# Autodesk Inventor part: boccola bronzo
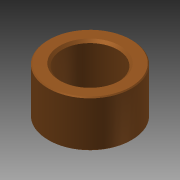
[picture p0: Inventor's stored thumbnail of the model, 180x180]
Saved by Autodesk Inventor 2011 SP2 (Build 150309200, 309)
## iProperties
Created: 2018-03
Part Number: boccola bronzo
Document SubType Name: Modeling
Designer: 18619647
Density: 1 g/cm^3
Author: 18619647
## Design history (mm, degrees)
sketch "Schizzo1"
  geometry: C1 r 6 at (0, 0); C2 r 9 at (0, 0); 1 further point
  constraints: 2 centre point, 2 coincident
  dimensions: "d0" = 12 diameter of C1; "d1" = 18 diameter of C2
extrude "Estrusione1" new body sketch "Schizzo1" distance "d2" = 10; taper "d3" = 0 deg
chamfer "Smusso1" distance "d4" = 0.5; stored, may be unused: second distance "d5" = 2, angle "d6" = 45 deg
chamfer "Smusso2" distance "d7" = 0.2; stored, may be unused: second distance "d8" = 2, angle "d9" = 45 deg
node "Solido1"
